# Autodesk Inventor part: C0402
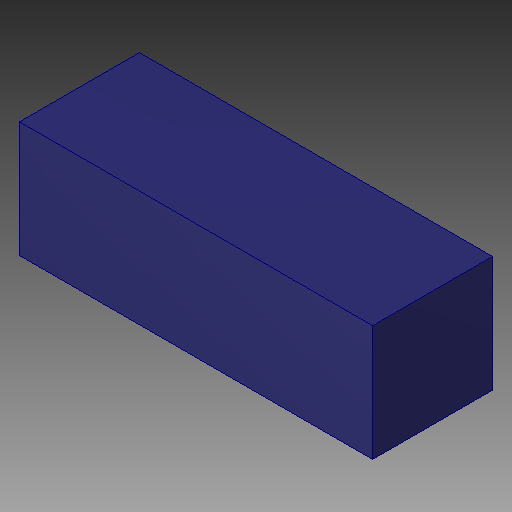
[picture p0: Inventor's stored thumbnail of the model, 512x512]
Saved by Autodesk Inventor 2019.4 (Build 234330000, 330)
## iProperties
Created: 2019-11
Part Number: C0402
Material: Generic
Document SubType Name: Modeling
Designer: Willist
Density: 1 g/cm^3
Appearance: C0402, C0402
Author: Willist
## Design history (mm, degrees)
sketch "C0402, C0402_1"
  geometry: L1 (-1.473, 0.483)-(1.473, 0.483); L2 (1.473, 0.483)-(1.473, -0.483); L3 (1.473, -0.483)-(-1.473, -0.483); L4 (-1.473, -0.483)-(-1.473, 0.483)
  constraints: 8 end point
extrude "Extrusion1" join sketch "C0402, C0402_1" distance "d0" = 1; taper "d1" = 0 deg
body "Solid1"
